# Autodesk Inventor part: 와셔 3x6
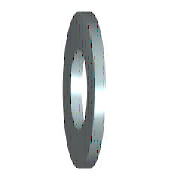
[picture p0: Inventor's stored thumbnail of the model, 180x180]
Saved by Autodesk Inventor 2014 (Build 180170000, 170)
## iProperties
IsCustomPart: 0
Created: 2012-02
Part Number: 와셔 3x6
Material: 강철, 연강
Description: 평면 와셔
Document SubType Name: Modeling
Standard: KS B 1326
Designer: mduedu
Standards Organization: KS
Language: ko-KR
Size Designation: 3x6
Categories: <MemberInstance><Categories><Category DisplayName="조임쇠" InternalName="e4da775c-781d-43d5-af7c-5136215cf5a6" Mnemonic="FSTN"><Category DisplayName="와셔" InternalN
Density: 7.86 g/cm^3
Mass: 0.0795112 g
Surface Area: 0.54915 cm^2
Volume: 0.0101159 cm^3
Appearance: 파란색 - 벽 페인트 - 광택
Author: mduedu
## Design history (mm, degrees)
sketch "스케치"
  geometry: C1 r 3 at (0, 0); C2 r 1.6 at (0, 0); 1 further point
  constraints: 2 centre point, 2 coincident
  dimensions: "d0" = 3.2 diameter of C2 (= SD1); "d1" = 6 diameter of C1 (= SD2)
extrude "본체" new body sketch "스케치" distance "d2" = 0.5 (= SD); taper "d3" = 0 deg
workaxis "Work Axis1"
workplane "Work Plane1"
body "Solid1"
other parameters: "SD1" = 3.2 [user parameter; used in 1 equation term], "SD2" = 6 [user parameter; used in 1 equation term], "SD" = 0.5 [user parameter; used in 1 equation term], "d4" = 0, "d5" = 0, "d6" = 0, "d7" = 0, "NND" = 3 [user parameter]
